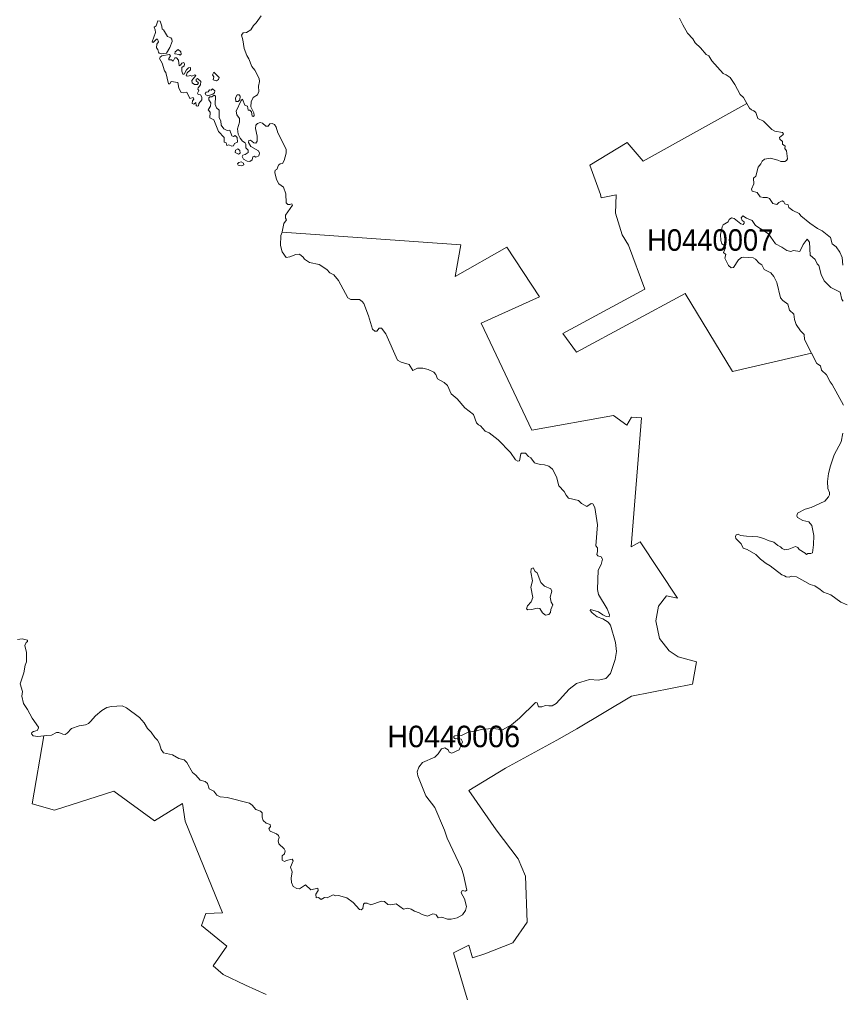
# Model space of a CAD drawing. Extents: x 369010 to 739155, y 6377141 to 6616555.
# Drawn here: x 374669 to 378495, y 6463309 to 6467832 of the extents above; entities that cross this region are included whole.
import ezdxf
from ezdxf.enums import TextEntityAlignment as Align

# ---------------------------------------------------------------- set-up
doc = ezdxf.new("R2010")
doc.units = 0
doc.header["$LTSCALE"] = 40
doc.layers.add('1', color=7, linetype='Continuous', lineweight=13)
doc.layers.add('2', color=7, linetype='Continuous')

msp = doc.modelspace()

# ---------------------------------------------------------------- linework, layer by layer
at = {"layer": '1'}
for points in [[(375322.53, 6467825.1), (375312.1, 6467825.92), (375303.83, 6467803.42), (375295.22, 6467796.8), (375300.19, 6467784.38), (375300.85, 6467771.14), (375285.62, 6467727.78), (375290.26, 6467725.13), (375306.14, 6467741.02), (375310.78, 6467741.02), (375314.75, 6467728.44), (375308.13, 6467717.85), (375305.81, 6467700.47), (375312.76, 6467693.52), (375314.75, 6467680.61), (375318.72, 6467675.65), (375327.16, 6467672.67), (375351.99, 6467676.31), (375367.55, 6467702.46), (375379.13, 6467730.76), (375377.81, 6467740.36), (375373.17, 6467746.65), (375356.29, 6467753.6), (375338.09, 6467784.38), (375331.8, 6467787.36), (375330.47, 6467801.43)], [(375411.4, 6467669.36), (375415.87, 6467666.38), (375421, 6467671.01), (375419.68, 6467681.6), (375407.1, 6467692.53), (375393.03, 6467681.77), (375390.72, 6467673.33)], [(375398.33, 6467654.46), (375391.38, 6467653.47), (375382.77, 6467638.57), (375375.82, 6467645.19), (375363.91, 6467644.53), (375363.91, 6467650.49), (375371.52, 6467664.06), (375366.22, 6467670.02), (375331.14, 6467662.74), (375322.2, 6467657.11), (375320.54, 6467651.48), (375332.96, 6467629.14), (375343.71, 6467593.72), (375349.01, 6467585.45), (375361.92, 6467533.31), (375367.22, 6467533.64), (375374.5, 6467543.57), (375405.78, 6467539.27), (375409.58, 6467512.79), (375421, 6467493.26), (375429.11, 6467490.94), (375446.16, 6467494.25), (375460.56, 6467464.79), (375476.12, 6467469.1), (375479.92, 6467461.48), (375473.8, 6467454.37), (375471.81, 6467441.13), (375479.92, 6467438.64), (375488.53, 6467446.26), (375490.35, 6467433.02), (375495.65, 6467430.04), (375501.27, 6467431.53), (375502.27, 6467441.46), (375516, 6467459.5), (375516.5, 6467470.92), (375509.71, 6467482.83), (375499.62, 6467484.32), (375496.31, 6467490.45), (375502.93, 6467501.87), (375498.29, 6467507.66), (375499.29, 6467515.11), (375510.21, 6467529.01), (375511.53, 6467544.24), (375496.31, 6467558.47), (375490.18, 6467555.66), (375490.18, 6467546.55), (375501.6, 6467537.95), (375496.31, 6467529.84), (375483.07, 6467529.84), (375471.65, 6467537.12), (375470.66, 6467548.04), (375488.7, 6467571.21), (375484.39, 6467575.52), (375470.66, 6467568.4), (375464.04, 6467571.21), (375451.62, 6467568.4), (375444.51, 6467570.72), (375447.82, 6467583.63), (375464.04, 6467598.36), (375463.54, 6467609.28), (375454.1, 6467607.46), (375445, 6467597.86), (375434.58, 6467578.83), (375428.45, 6467578.33), (375423.16, 6467592.23), (375424.15, 6467608.78), (375434.08, 6467616.89), (375436.06, 6467625), (375432.26, 6467631.62), (375423.16, 6467629.8), (375417.03, 6467619.21), (375411.74, 6467617.39), (375408.76, 6467642.88)], [(375571.94, 6467588.1), (375566.98, 6467575.02), (375572.61, 6467565.09), (375569.3, 6467551.35), (375584.52, 6467547.05), (375593.46, 6467553.67), (375596.44, 6467562.77)], [(375566.65, 6467509.98), (375560.52, 6467504.18), (375552.41, 6467505.18), (375546.79, 6467495.25), (375537.19, 6467493.76), (375532.88, 6467488.96), (375534.87, 6467481.51), (375543.81, 6467478.03), (375567.14, 6467485.32), (375575.25, 6467491.44), (375577.07, 6467501.37)], [(375655.36, 6467242.85), (375663.47, 6467245.67), (375668.1, 6467255.27), (375681.84, 6467261.89), (375680.51, 6467283.73), (375671.74, 6467292.67), (375663.63, 6467289.03), (375655.52, 6467290.85), (375646.92, 6467317.99), (375634.67, 6467317), (375618.45, 6467324.12), (375606.2, 6467340.34), (375605.21, 6467361.69), (375596.6, 6467375.42), (375597.6, 6467410.18), (375584.69, 6467421.6), (375578.07, 6467436.82), (375580.88, 6467476.21), (375573.76, 6467480.02), (375563.34, 6467472.41), (375553.9, 6467472.9), (375549.1, 6467468.1), (375549.1, 6467459.5), (375559.03, 6467444.44), (375556.22, 6467429.21), (375545.3, 6467412.5), (375555.06, 6467401.08), (375554.57, 6467375.42), (375572.61, 6467365.99), (375593.96, 6467312.2), (375621.1, 6467283.24), (375620.6, 6467261.39), (375629.7, 6467258.58), (375633.51, 6467246.66), (375641.95, 6467248.98)], [(375684.98, 6467450.56), (375693.59, 6467459.5), (375694.58, 6467475.22), (375689.78, 6467482.83), (375681.18, 6467482.83), (375672.74, 6467467.61), (375675.05, 6467451.55)], [(375687.63, 6467205.78), (375694.25, 6467210.58), (375692.93, 6467223.32), (375683.33, 6467230.94), (375673.4, 6467225.31), (375671.91, 6467214.39)], [(375700.54, 6467151.66), (375711.79, 6467156.3), (375710.47, 6467164.9), (375700.04, 6467171.02), (375688.13, 6467167.71), (375682.83, 6467160.6), (375685.81, 6467154.47)], [(377113.78, 6465063.33), (377130.49, 6465066.64), (377138.11, 6465076.08), (377138.6, 6465089.98), (377149.03, 6465111.33), (377140.43, 6465124.07), (377135.96, 6465146.08), (377143.07, 6465174.55), (377138.77, 6465185.47), (377109.31, 6465197.89), (377093.09, 6465215.43), (377075.55, 6465260.61), (377066.94, 6465266.24), (377057.01, 6465283.78), (377047.58, 6465278.65), (377045.43, 6465262.93), (377054.03, 6465223.04), (377045.92, 6465193.09), (377055.36, 6465144.59), (377047.25, 6465124.57), (377030.2, 6465107.02), (377025.9, 6465092.79), (377032.52, 6465087.5), (377051.05, 6465088.98), (377074.89, 6465096.1), (377088.13, 6465094.28), (377101.04, 6465074.25)]]:
    msp.add_lwpolyline(points, close=True, dxfattribs=at)
for points in [[(375792.89, 6467849.76), (375769.06, 6467816.66), (375756.48, 6467805.07), (375743.9, 6467783.72), (375724.87, 6467771.8), (375709.31, 6467769.98), (375701.2, 6467759.39), (375707.82, 6467737.55), (375713.12, 6467698.16), (375725.37, 6467665.39), (375735.46, 6467650.16), (375749.2, 6467614.08), (375762.27, 6467597.36), (375783.13, 6467558.47), (375784.62, 6467543.74), (375779.82, 6467522.39), (375781.31, 6467498.06), (375775.84, 6467481.51), (375754.83, 6467469.1), (375746.72, 6467449.57), (375744.9, 6467426.23), (375758.63, 6467397.77)], [(377763.71, 6466558.66), (377259.09, 6466285.25), (377194.38, 6466372.47), (377575.54, 6466579.35), (377499.73, 6466782.75), (377471.43, 6466830.75), (377439.66, 6466931.71), (377443.3, 6467017.77), (377372.63, 6467003.53), (377369.98, 6467018.26), (377319.67, 6467154.81), (377494.27, 6467260.07), (377568.09, 6467174.17), (378050.53, 6467441.29), (378035.14, 6467469.76), (378019.91, 6467483.5), (377993.76, 6467530.67), (377973.24, 6467561.95), (377954.21, 6467575.35), (377939.48, 6467580.98), (377888.17, 6467639.4), (377872.95, 6467662.74), (377861.53, 6467669.85), (377835.05, 6467701.3), (377810.39, 6467724.47), (377799.96, 6467742.34), (377773.81, 6467769.49), (377752.29, 6467806.73), (377737.07, 6467838.5)], [(375758.63, 6467397.77), (375760.62, 6467385.52), (375756.81, 6467380.72), (375750.52, 6467383.53), (375747.71, 6467402.57), (375739.6, 6467410.18), (375731.99, 6467411.5), (375728.68, 6467429.71), (375716.93, 6467433.85), (375705.01, 6467461.48), (375699.22, 6467456.19), (375676.87, 6467405.88), (375679.36, 6467389.16), (375691.27, 6467371.62), (375691.27, 6467355.07), (375682.67, 6467324.61), (375685.48, 6467299.95), (375695.41, 6467280.92), (375705.51, 6467266.69), (375717.75, 6467259.57), (375720.73, 6467252.29), (375721.06, 6467235.74), (375732.15, 6467224.32), (375731.66, 6467213.89), (375718.75, 6467203.96), (375707.33, 6467201.97), (375704.51, 6467194.86), (375709.81, 6467182.44), (375727.85, 6467174), (375739.27, 6467171.52), (375750.52, 6467180.62), (375754.33, 6467193.37), (375760.12, 6467196.35), (375768.23, 6467192.87), (375780.98, 6467198.17), (375784.78, 6467210.58), (375780.48, 6467222), (375744.4, 6467241.36), (375732.98, 6467259.9), (375735.79, 6467269), (375743.07, 6467271.32), (375759.13, 6467259.07), (375767.24, 6467258.08), (375773.86, 6467267.02), (375773.86, 6467290.35), (375766.74, 6467326.1), (375768.23, 6467340.83), (375775.35, 6467349.27), (375787.26, 6467353.08), (375798.52, 6467350.76), (375814.74, 6467336.03), (375825.16, 6467336.53), (375833.27, 6467346.96), (375843.2, 6467349.27), (375854.62, 6467344.64), (375862.24, 6467331.23), (375869.35, 6467306.08), (375908.91, 6467229.12), (375909.41, 6467211.57), (375899.81, 6467177.31), (375892.19, 6467162.09), (375880.77, 6467160.6), (375872.66, 6467154.47), (375865.55, 6467135.44), (375857.6, 6467131.64), (375856.11, 6467121.7), (375863.73, 6467088.94), (375874.65, 6467068.91), (375896.5, 6467052.69), (375906.92, 6467021.91), (375909.41, 6466980.53), (375917.02, 6466971.92), (375925.96, 6466971.92), (375935.39, 6466975.23), (375938.37, 6466968.61), (375905.1, 6466922.93), (375905.1, 6466908.7), (375910.73, 6466901.58), (375897.49, 6466884.04), (375889.88, 6466844.65), (375889.38, 6466843), (376720.38, 6466784.08), (376694.39, 6466637.61), (376934.04, 6466773.82), (377086.8, 6466542.61), (376815.04, 6466420.63), (377050.72, 6465923.79), (377429.89, 6465991.15), (377492.12, 6465946.79), (377514.8, 6465984.03), (377559.81, 6465981.05), (377512.64, 6465381.26), (377554.02, 6465404.27), (377727.63, 6465142.44), (377676.66, 6465153.03), (377638.92, 6465105.37), (377627.67, 6465036.35), (377644.38, 6464953.93), (377689.73, 6464897.33), (377731.11, 6464869.03)], [(378050.53, 6467441.29), (377568.09, 6467174.17), (377494.27, 6467260.07), (377319.67, 6467154.81), (377369.98, 6467018.26), (377372.63, 6467003.53), (377443.3, 6467017.77), (377439.66, 6466931.71), (377471.43, 6466830.75), (377499.73, 6466782.75), (377575.54, 6466579.35), (377194.38, 6466372.47), (377259.09, 6466285.25), (377763.71, 6466558.66), (377983.83, 6466195.88), (378351.25, 6466281.28), (378318.48, 6466344.66), (378316, 6466368.5), (378300.44, 6466385.21), (378279.42, 6466415), (378272.31, 6466437.84), (378269, 6466462.67), (378248.64, 6466481.7), (378241.03, 6466509.17), (378217.19, 6466525.89), (378207.26, 6466537.64), (378189.55, 6466609.47), (378175.32, 6466637.94), (378161.09, 6466654.16), (378130.64, 6466670.38), (378120.71, 6466691.23), (378107.96, 6466699.34), (378091.25, 6466718.37), (378079.33, 6466724.5), (378036.13, 6466727.31), (378025.21, 6466725.49), (378011.97, 6466714.56), (377987.64, 6466678.82), (377976.72, 6466678.32), (377964.8, 6466687.92), (377947.26, 6466723.01), (377953.05, 6466739.23), (377941.63, 6466749.16), (377951.06, 6466770.17), (377945.77, 6466781.59), (377934.02, 6466788.71), (377928.72, 6466804.76), (377928.22, 6466832.9), (377934.84, 6466867.99), (377940.64, 6466877.59), (377963.97, 6466891.82), (377967.45, 6466903.24), (377978.37, 6466909.86), (377991.78, 6466907.05), (378023.06, 6466882.22), (378032.49, 6466879.9), (378038.28, 6466884.7), (378037.29, 6466891.82), (378029.18, 6466898.44), (378023.55, 6466910.85), (378031.17, 6466919.79), (378049.21, 6466908.37), (378074.36, 6466897.12), (378090.09, 6466875.1), (378150.66, 6466835.22), (378182.93, 6466789.54), (378212.89, 6466773.48), (378236.23, 6466758.75), (378254.43, 6466753.95), (378266.85, 6466757.76), (378296.8, 6466754.45), (378312.03, 6466786.23), (378330.07, 6466810.56), (378341.98, 6466797.15), (378345.29, 6466736.91), (378367.64, 6466715.89), (378376.91, 6466696.53), (378384.52, 6466688.42), (378395.94, 6466647.04), (378410.17, 6466618.08), (378441.45, 6466586.13), (378484.32, 6466564.29), (378492.1, 6466531.02), (378498.72, 6466522.58)], [(378493.25, 6466726.48), (378483.32, 6466751.14), (378465.28, 6466774.81), (378447.24, 6466789.21), (378439.8, 6466819.16), (378400.9, 6466850.44), (378378.56, 6466860.37), (378342.48, 6466885.2), (378300.61, 6466919.46), (378293.16, 6466930.38), (378263.37, 6466944.62), (378245.16, 6466958.85), (378241.85, 6466971.26), (378227.62, 6466974.57), (378222.49, 6466984.5), (378215.04, 6466988.81), (378199.32, 6466981.19), (378189.39, 6466972.09), (378171.85, 6466977.39), (378156.12, 6466999.73), (378144.21, 6467004.03), (378126.17, 6467004.53), (378112.43, 6467008.17), (378097.7, 6467028.2), (378075.36, 6467033.99), (378072.54, 6467043.92), (378082.97, 6467068.08), (378080.98, 6467094.23), (378091.58, 6467103.83), (378102.83, 6467145.54), (378114.75, 6467160.76), (378121.04, 6467173.67), (378132.79, 6467183.11), (378160.92, 6467187.41), (378194.19, 6467178.47), (378208.42, 6467171.69), (378226.46, 6467171.36), (378235.07, 6467176.49), (378239.37, 6467185.09), (378235.07, 6467222.17), (378226.46, 6467232.1), (378227.95, 6467243.52), (378215.54, 6467252.95), (378215.54, 6467264.87), (378203.62, 6467275.29), (378202.3, 6467284.4), (378217.36, 6467296.31), (378220.34, 6467301.11), (378215.54, 6467306.74), (378180.78, 6467312.86), (378167.05, 6467320.97), (378128.15, 6467359.04), (378101.51, 6467372.77), (378091.58, 6467400.41), (378083.14, 6467408.03), (378071.22, 6467412.66), (378062.28, 6467419.45), (378050.53, 6467441.29)], [(375889.38, 6466843), (375884.08, 6466827.94), (375882.26, 6466782.26), (375889.88, 6466751.97), (375908.91, 6466726.32), (375926.45, 6466728.63), (375953.1, 6466739.56), (375971.14, 6466741.38), (375987.69, 6466728.14), (375994.31, 6466718.21), (376016.65, 6466702.48), (376062.83, 6466693.38), (376097.09, 6466669.71), (376111.82, 6466654.98), (376129.86, 6466644.89), (376151.54, 6466618.9), (376195.23, 6466538.97), (376209.96, 6466530.86), (376249.35, 6466530.03), (376261.76, 6466521.42), (376269.38, 6466511.49), (376291.72, 6466454.89), (376310.26, 6466392.99), (376320.19, 6466383.06), (376330.61, 6466383.06), (376340.54, 6466397.79), (376352.46, 6466396.96), (376371.49, 6466371.64), (376426.61, 6466249), (376443.32, 6466238.58), (376479.9, 6466227.65), (376496.95, 6466200.18), (376519.79, 6466211.6), (376543.95, 6466210.61), (376568.61, 6466205.81), (376594.76, 6466193.06), (376604.85, 6466181.15), (376612.8, 6466161.12), (376643.25, 6466145.4), (376657.98, 6466131.16), (376675.19, 6466091.77), (376703.66, 6466068.93), (376739.74, 6466027.06), (376779.13, 6465995.78), (376793.03, 6465957.72), (376802.47, 6465947.78), (376812.07, 6465943.98), (376834.41, 6465918.82), (376851.95, 6465910.71), (376894.16, 6465877.94), (376951.75, 6465819.85), (376975.42, 6465784.76), (376986.34, 6465779.47), (376993.46, 6465780.46), (376999.25, 6465813.23), (377002.56, 6465816.54), (377020.6, 6465815.55), (377035.33, 6465799.99), (377045.76, 6465795.19), (377063.47, 6465771.03), (377089.45, 6465763.41), (377108.98, 6465761.92), (377129.5, 6465755.3), (377146.55, 6465741.4), (377165.09, 6465706.31), (377176.5, 6465663.95), (377201.66, 6465638.29), (377210.76, 6465621.25), (377221.69, 6465607.51), (377267.2, 6465596.09), (377281.6, 6465581.86), (377306.76, 6465568.45), (377326.62, 6465582.19), (377334.73, 6465580.37), (377343.83, 6465564.15), (377355.25, 6465482.88), (377347.64, 6465385.9), (377356.57, 6465375.97), (377356.57, 6465359.75), (377352.77, 6465344.69), (377358.06, 6465338.9), (377372.79, 6465334.59), (377378.92, 6465323.17), (377373.79, 6465298.02), (377359.88, 6465272.36), (377356.57, 6465182.49), (377360.88, 6465159.32), (377400.76, 6465092.29), (377411.19, 6465064.16), (377409.87, 6465055.72), (377396.13, 6465057.54), (377380.41, 6465064.66), (377361.37, 6465078.06), (377322.81, 6465089.81), (377321.49, 6465084.68), (377330.92, 6465073.76), (377354.75, 6465056.05), (377381.4, 6465046.62), (377405.07, 6465030.07), (377416.98, 6465016.16)], [(376686.94, 6463493.36), (376757.28, 6463528.28), (376775.65, 6463469.69), (376832.09, 6463489.06), (376962.18, 6463540.36), (377029.04, 6463635.86), (377020.77, 6463849.69), (376986.51, 6463929.63), (376884.89, 6464065.34), (376758.61, 6464247.56), (376928.08, 6464351), (377167.73, 6464481.92), (377260.08, 6464535.04), (377514.8, 6464687.14), (377797.14, 6464741.76), (377816.01, 6464846.02), (377731.11, 6464869.03), (377689.73, 6464897.33), (377644.38, 6464953.93), (377627.67, 6465036.35), (377638.92, 6465105.37), (377676.66, 6465153.03), (377727.63, 6465142.44), (377554.02, 6465404.27), (377512.64, 6465381.26), (377559.81, 6465981.05), (377514.8, 6465984.03), (377492.12, 6465946.79), (377429.89, 6465991.15), (377050.72, 6465923.79), (376815.04, 6466420.63), (377086.8, 6466542.61), (376934.04, 6466773.82), (376694.39, 6466637.61), (376720.38, 6466784.08), (375889.38, 6466843)], [(378497.06, 6466690.73), (378493.25, 6466726.48)], [(378499.87, 6466039.64), (378447.24, 6466136.13), (378437.65, 6466147.88), (378420.1, 6466180.32), (378397.26, 6466202.16), (378392.63, 6466222.52), (378375.91, 6466233.44), (378351.25, 6466281.28), (377983.83, 6466195.88), (377763.71, 6466558.66)], [(378516.09, 6465111.33), (378487.63, 6465122.75), (378440.29, 6465158.33), (378407.03, 6465169.25), (378391.3, 6465182.66), (378365.65, 6465198.71), (378345.29, 6465205), (378281.41, 6465241.58), (378257.58, 6465243.9), (378247.15, 6465239.59), (378233.41, 6465240.59), (378225.3, 6465246.38), (378212.89, 6465250.19), (378159.27, 6465292.39), (378139.74, 6465302.82), (378114.09, 6465322.84), (378092.24, 6465345.18), (378051.36, 6465368.52), (378033.32, 6465374.64), (378024.22, 6465395), (378009.49, 6465408.9), (377998.56, 6465418.83), (377997.57, 6465428.27), (378000.88, 6465435.88), (378010.48, 6465438.86), (378020.41, 6465433.56), (378048.05, 6465430.25), (378101.18, 6465427.94), (378129.81, 6465418.83), (378149.67, 6465410.23), (378175.82, 6465402.61), (378193.86, 6465387.39), (378207.26, 6465380.27), (378213.88, 6465372.66), (378227.12, 6465367.53), (378245.66, 6465369.85), (378276.11, 6465382.75), (378287.04, 6465377.46), (378292.83, 6465369.02), (378320.8, 6465351.81), (378327.42, 6465345.18), (378334.54, 6465349.49), (378347.94, 6465348.99), (378355.56, 6465353.29), (378360.19, 6465389.37), (378361.18, 6465433.56), (378352.58, 6465479.24), (378337.85, 6465496.29), (378309.88, 6465503.9), (378286.04, 6465516.32), (378282.24, 6465524.43), (378286.04, 6465537.17), (378321.79, 6465555.71), (378348.77, 6465563.32), (378412.49, 6465592.28), (378430.53, 6465613.8), (378433.84, 6465622.74), (378434.34, 6465633.66), (378426.23, 6465651.7), (378424.9, 6465684.14), (378429.2, 6465721.54), (378438.64, 6465757.29), (378456.68, 6465808.6), (378488.12, 6465868.51), (378496.07, 6465908.4)], [(377416.98, 6465016.16), (377440.32, 6464936.39), (377444.95, 6464893.52), (377438.83, 6464856.95), (377416.98, 6464791.91), (377394.64, 6464769.07), (377360.88, 6464761.45), (377319, 6464764.27), (377258.26, 6464745.23), (377224.5, 6464718.75), (377164.59, 6464652.55), (377145.06, 6464642.12), (377130, 6464640.8), (377114.28, 6464643.61), (377097.06, 6464637.49), (377082.33, 6464636.99), (377075.22, 6464655.53), (377067.44, 6464657.35), (376992.8, 6464583.7), (376955.72, 6464552.75), (376914.18, 6464530.41), (376872.81, 6464535.7), (376826.8, 6464533.39), (376750.99, 6464517.17), (376723.85, 6464504.26), (376692.57, 6464501.94), (376687.77, 6464499.13), (376687.77, 6464493), (376695.38, 6464488.7), (376704.82, 6464490.03), (376722.86, 6464486.22), (376729.15, 6464473.97), (376713.42, 6464436.4), (376678.17, 6464421.18), (376666.42, 6464425.48), (376661.13, 6464437.73), (376646.4, 6464446.33), (376630.51, 6464441.2), (376615.28, 6464417.87), (376599.06, 6464402.14), (376543.12, 6464377.98), (376524.92, 6464355.97), (376518.3, 6464335.11), (376520.28, 6464316.08), (376558.02, 6464223.9), (376599.89, 6464169.28), (376645.24, 6464063.69), (376657.65, 6464026.28), (376723.85, 6463885.11), (376733.62, 6463855.15), (376747.85, 6463784.32), (376742.22, 6463780.01), (376726.5, 6463782.33), (376722.69, 6463771.41), (376738.42, 6463744.43), (376746.86, 6463708.18), (376741.89, 6463690.64), (376727.66, 6463669.29), (376703.99, 6463656.38), (376676.35, 6463649.76), (376658.31, 6463649.76), (376632.16, 6463658.86), (376614.62, 6463656.05), (376605.52, 6463669.29), (376598.73, 6463673.59), (376590.12, 6463674.09), (376565.3, 6463663.5), (376541.14, 6463671.61), (376526.41, 6463679.72), (376504.56, 6463686.83), (376489.33, 6463696.43), (376474.11, 6463700.57), (376454.41, 6463696.93), (376419.66, 6463721.09), (376394.5, 6463715.8), (376381.75, 6463717.29), (376365.87, 6463731.52), (376351.14, 6463733.51), (376302.64, 6463715.8), (376284.6, 6463724.4), (376272.19, 6463724.4), (376268.88, 6463718.78), (376265.07, 6463699.74), (376257.46, 6463692.63), (376249.85, 6463694.94), (376220.39, 6463727.71), (376191.09, 6463748.24), (376151.21, 6463759.16), (376140.28, 6463757.67), (376127.54, 6463762.47), (376098.91, 6463749.06), (376087.49, 6463750.55), (376071.93, 6463740.62), (376058.53, 6463750.06), (376048.1, 6463749.56), (376046.61, 6463765.28), (376058.03, 6463783.32), (376055.22, 6463793.75), (376023.44, 6463785.81), (375997.79, 6463809.47)], [(375816.39, 6463298.89), (375720.07, 6463343.08), (375616.3, 6463392.57), (375569.13, 6463433.28), (375633.35, 6463523.48), (375514.51, 6463620.8), (375535.2, 6463675.58), (375612.66, 6463679.22), (375439.54, 6464105.06), (375426.3, 6464188.15), (375296.21, 6464106.88), (375107.54, 6464244.75), (374830.98, 6464156.37), (374727.21, 6464186.49), (374782.66, 6464502.44), (374782.66, 6464502.44), (374754.68, 6464498.47), (374732.34, 6464502.77), (374724.73, 6464511.71), (374726.05, 6464517.66), (374734.66, 6464522.63), (374751.04, 6464527.43), (374757.33, 6464537.36), (374758, 6464542.66), (374728.37, 6464584.69), (374706.52, 6464624.91), (374687.32, 6464652.72), (374680.37, 6464685.82), (374682.36, 6464707.5), (374672.76, 6464743.91), (374689.64, 6464794.72), (374695.93, 6464831.13), (374700.9, 6464845.69), (374701.89, 6464889.22), (374693.28, 6464922.32), (374700.57, 6464935.4), (374706.19, 6464940.36), (374706.52, 6464946.32), (374681.04, 6464952.94), (374659.35, 6464950.29)], [(377731.11, 6464869.03), (377816.01, 6464846.02), (377797.14, 6464741.76), (377514.8, 6464687.14), (377260.08, 6464535.04), (377167.73, 6464481.92), (376928.08, 6464351), (376758.61, 6464247.56), (376884.89, 6464065.34), (376986.51, 6463929.63), (377020.77, 6463849.69), (377029.04, 6463635.86), (376962.18, 6463540.36), (376832.09, 6463489.06), (376775.65, 6463469.69), (376757.28, 6463528.28), (376686.94, 6463493.36), (376767.88, 6463221.93)], [(375997.79, 6463809.47), (375971.14, 6463791.43), (375957.9, 6463792.43), (375941.68, 6463802.36), (375933.57, 6463820.4), (375931.75, 6463839.93), (375936.38, 6463869.39), (375928.77, 6463892.23), (375940.69, 6463921.69), (375935.89, 6463928.31), (375910.23, 6463923.01), (375900.8, 6463917.88), (375889.38, 6463923.51), (375890.37, 6463944.52), (375901.3, 6463952.97), (375903.61, 6463967.7), (375899.31, 6463977.29), (375874.15, 6463999.64), (375870.84, 6464014.37), (375875.64, 6464030.09), (375873.49, 6464039.03), (375864.06, 6464046.64), (375833.61, 6464059.55), (375828.31, 6464069.98), (375836.42, 6464079.91), (375833.61, 6464089.51), (375815.07, 6464095.63), (375802.16, 6464108.04), (375796.53, 6464124.1), (375796.53, 6464144.12), (375789.91, 6464151.74), (375768.4, 6464160.18), (375751.35, 6464179.71), (375738.44, 6464189.3), (375634.17, 6464215.45), (375602.4, 6464217.77), (375585.68, 6464225.88), (375571.78, 6464245.25), (375550.43, 6464256.17), (375543.64, 6464280.99), (375531.89, 6464289.1), (375508.56, 6464296.72), (375489.03, 6464319.89), (375472.48, 6464331.31), (375447.15, 6464378.81), (375434.58, 6464389.73), (375409.42, 6464397.34), (375380.95, 6464413.56), (375338.58, 6464423.16), (375328.16, 6464437.89), (375319.22, 6464464.87), (375309.95, 6464481.92), (375298.53, 6464493.83), (375281.65, 6464518.99), (375264.44, 6464536.7), (375248.88, 6464563.18), (375227.53, 6464586.68), (375166.62, 6464632.86), (375146.27, 6464641.46), (375095.95, 6464639.14), (375075.43, 6464634.18), (375051.1, 6464620.28), (375021.64, 6464594.96), (374999.47, 6464568.14), (374989.37, 6464559.54), (374975.14, 6464553.58), (374946.01, 6464548.95), (374910.92, 6464536.37), (374890.56, 6464514.35), (374880.63, 6464508.73), (374870.04, 6464509.06), (374851.5, 6464517.33), (374840.91, 6464517), (374817.58, 6464504.76), (374793.41, 6464504.09), (374782.66, 6464502.44), (374782.66, 6464502.44), (374727.21, 6464186.49), (374830.98, 6464156.37), (375107.54, 6464244.75), (375296.21, 6464106.88), (375426.3, 6464188.15), (375439.54, 6464105.06), (375612.66, 6463679.22), (375535.2, 6463675.58), (375514.51, 6463620.8), (375633.35, 6463523.48), (375569.13, 6463433.28), (375616.3, 6463392.57), (375720.07, 6463343.08), (375816.39, 6463298.89)], [(376767.88, 6463221.93), (376686.94, 6463493.36)]]:
    msp.add_lwpolyline(points, dxfattribs=at)

# ---------------------------------------------------------------- texts
at = {"layer": '2', "width": 0.95}
msp.add_text('H0440007', height=100, dxfattribs=at).set_placement((377880.22, 6466757.11), align=Align.CENTER)
at = {"layer": '2'}
msp.add_text('H0440006', height=100, dxfattribs=at).set_placement((376687.78, 6464449.13), align=Align.CENTER)

doc.saveas('drawing.dxf')
